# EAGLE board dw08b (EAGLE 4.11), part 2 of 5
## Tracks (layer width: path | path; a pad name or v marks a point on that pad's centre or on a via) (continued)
N_ADD00  (via drill 0.61) (continued)
  Bottom 0.305: v76.2,63.25 79.25,63.25 79.5,63.5 82.3,63.5 82.55,63.25 85.6,63.25 85.85,63.5 88.65,63.5 88.9,63.25 91.95,63.25 92.2,63.5 95,63.5 95.25,63.25 98.3,63.25 98.55,63.5 v99.57,63.5 | v99.57,72.39 99.82,72.64 116.59,72.64 117.09,72.14 119.38,72.14 119.89,72.64 126.49,72.64 127.76,71.37 156.46,71.37 v156.72,71.63 | v163.07,70.87 163.32,71.12 164.34,71.12 164.59,71.37 171.7,71.37 172.21,71.88 177.29,71.88 177.55,72.14 191.52,72.14 | 191.52,72.14 196.09,72.14 v196.34,71.88 | v197.61,60.45 199.64,60.45 200.15,59.94 v200.91,59.94 | v200.91,57.15 202.95,57.15 203.2,56.9 206.25,56.9 206.5,57.15 209.3,57.15 209.55,56.9 212.6,56.9 212.85,57.15 215.65,57.15 217.17,55.63 219.96,55.63 B07.D2 | v215.9,125.48 219.96,125.48 A07.D2 | v215.65,115.32 214.63,114.3 212.6,114.3 212.34,114.05 209.55,114.05 209.3,114.3 206.25,114.3 205.99,114.05 203.2,114.05 202.95,114.3 199.9,114.3 199.64,114.05 196.85,114.05 196.6,114.3 193.55,114.3 193.29,114.05 190.5,114.05 190.25,114.3 187.2,114.3 186.94,114.05 184.15,114.05 183.9,114.3 180.85,114.3 180.59,114.05 v177.8,114.05 | 191.52,72.14 v191.52,71.88
N_ADD01  (via drill 0.61)
  Top 0.305: v77.72,56.9 77.72,53.09 B19.E1 | v82.3,57.15 82.3,60.2 82.55,60.45 82.55,63.25 82.04,63.75 82.04,71.88 81.79,72.14 81.79,78.74 v82.04,78.99 | v163.83,72.14 v163.83,76.2 | v203.2,120.4 203.2,117.35 202.95,117.09 202.95,114.3 203.2,114.05 203.2,111 202.95,110.74 202.95,107.95 203.2,107.7 203.2,104.65 202.95,104.39 202.95,101.6 203.45,101.09 203.45,96.27 204.22,95.5 v204.22,92.2 | v201.93,88.9 v201.93,91.69 | v204.22,82.55 203.96,82.3 203.96,72.39 v204.22,72.14
  2 0.305: v201.93,88.9 203.2,87.63 203.2,85.6 202.69,85.09 202.95,84.84 202.95,83.82 v204.22,82.55
  15 0.305: v210.06,72.14 213.87,68.33 213.87,66.8 215.65,65.02 215.65,63.5 224.28,54.86 224.28,53.09 B07.E2
  Bottom 0.305: v77.72,56.9 79.25,56.9 79.5,57.15 v82.3,57.15 | v82.04,78.99 82.3,78.74 92.96,78.74 93.22,78.99 100.84,78.99 101.09,79.25 102.11,79.25 103.38,77.98 119.89,77.98 120.14,78.23 121.16,78.23 122.43,76.96 132.33,76.96 132.59,77.22 151.89,77.22 153.16,75.95 163.58,75.95 v163.83,76.2 | v163.83,72.14 171.45,72.14 171.96,72.64 177.04,72.64 177.29,72.9 199.14,72.9 199.9,72.14 v204.22,72.14 v210.06,72.14 | v203.2,120.4 205.99,120.4 206.25,120.65 209.3,120.65 209.55,120.4 212.34,120.4 212.6,120.65 215.65,120.65 215.9,120.4 218.69,120.4 220.47,122.17 223.27,122.17 A07.E2 | v204.22,92.2 203.2,92.2 202.69,91.69 v201.93,91.69
N_ADD02  (via drill 0.61)
  Top 0.305: v205.49,68.07 205.74,68.33 205.74,82.3 v205.49,82.55 | v205.49,85.85 v205.49,88.65 | v210.82,92.2 v210.82,95 | v226.57,95.25 226.57,98.55 225.55,99.57 225.55,110.74 224.03,112.27 224.03,112.78 223.77,113.03 223.77,115.32 A07.H2 | v74.68,52.07 74.68,49.78 B19.F1 | v18.8,127 18.8,130.05 19.05,130.3 19.05,133.1 18.8,133.35 v18.8,140.46 | v201.42,66.8 v201.42,68.83
  2 0.305: v205.49,68.07 211.33,62.23 211.33,61.72 212.85,60.2 212.85,59.18 224.28,47.75 224.28,46.74 B07.H2 | v74.68,52.07 74.68,52.58 76.45,54.36 76.2,54.61 76.2,55.88 68.58,63.5 v66.04,63.5 | v51.82,80.01 51.82,80.26 49.02,83.06 48.77,83.06 48.26,83.57 48.26,85.34 43.43,90.17 v41.66,90.17 | v46.48,140.46 46.48,141.22 48.77,143.51 66.29,143.51 88.65,121.16 89.66,121.16 91.69,119.13 91.69,117.86 99.06,110.49 99.31,110.49 105.92,103.89 107.19,103.89 107.7,103.38 107.7,102.62 v117.86,92.46
  15 0.305: v64.52,63.5 56.39,71.63 51.31,71.63 47.5,75.44 47.5,77.22 49.28,78.99 50.55,78.99 51.56,80.01 v51.82,80.01 | v46.99,94.74 46.23,94.74 37.85,103.12 37.85,104.65 38.35,105.16 38.1,105.41 38.1,107.7 v18.8,127 | v123.19,92.2 123.7,92.2 127.25,88.65 v128.02,88.65 | v148.08,88.39 148.84,87.63 148.84,87.38 158.24,77.98 159.77,77.98 171.2,66.55 171.2,64.01 173.74,61.47 174.24,61.47 v175.51,60.2
  Bottom 0.305: v205.49,82.55 206.5,83.57 206.5,85.34 205.99,85.85 v205.49,85.85 | v205.49,88.65 206.25,88.65 209.8,92.2 v210.82,92.2 | v210.82,95 212.6,95 212.85,95.25 215.65,95.25 215.9,95 218.95,95 219.2,95.25 222,95.25 222.25,95 225.3,95 225.55,95.25 v226.57,95.25 | v64.52,63.5 v66.04,63.5 | v41.66,90.17 41.91,90.42 42.16,90.42 43.18,91.44 43.43,91.44 43.69,91.69 43.94,91.69 v46.99,94.74 | v18.8,140.46 25.65,140.46 25.91,140.72 46.23,140.72 v46.48,140.46 | v117.86,92.46 118.36,92.46 118.62,92.2 119.38,92.2 119.63,92.46 122.94,92.46 v123.19,92.2 | v128.02,88.65 130.05,88.65 130.3,88.9 133.1,88.9 133.35,88.65 136.4,88.65 136.65,88.9 139.45,88.9 139.7,88.65 142.75,88.65 143,88.9 145.8,88.9 146.3,88.39 v148.08,88.39 | v175.51,60.2 175.77,59.94 177.55,59.94 178.05,60.45 180.85,60.45 181.36,59.94 183.9,59.94 184.4,60.45 186.69,60.45 187.2,59.94 189.99,59.94 197.1,67.06 201.17,67.06 v201.42,66.8 | v201.42,68.83 201.68,68.58 204.47,68.58 204.72,68.33 205.23,68.33 v205.49,68.07
N_ADD03  (via drill 0.61)
  Top 0.305: 225.3,50.55 225.3,44.7 223.77,43.18 223.77,40.39 B07.K2 | 225.3,50.55 225.3,65.53 223.77,67.06 223.77,81.28 222.5,82.55 222.5,104.39 223.77,105.66 223.77,108.97 A07.K2 | v74.17,25.4 74.17,28.7 73.15,29.72 73.15,30.48 73.41,30.73 73.41,30.99 73.66,31.24 73.66,32.26 76.2,34.8 76.2,37.85 75.95,38.1 75.95,40.89 77.72,42.67 77.72,45.47 B19.H1 | v134.37,23.37 135.64,24.64 135.64,25.65 136.4,26.42 136.4,28.19 136.14,28.45 136.14,32 v136.91,32.77 | v146.05,33.27 146.3,33.53 146.3,34.04 148.08,35.81 149.61,35.81 151.38,34.04 v151.64,34.04 | v224.03,50.8 224.28,50.55 225.3,50.55
  2 0.305: v113.03,3.56 113.03,7.37 v115.82,10.16 | v114.05,27.43 113.54,27.43 110.74,30.23 110.74,31.5 111.51,32.26 111.25,32.51 111.25,34.8 110.74,35.31 110.74,38.1 111.76,39.12 111.76,39.88 113.79,41.91 115.57,41.91 120.65,36.83 120.65,34.8 120.14,34.29 120.4,34.04 120.4,33.02 121.16,32.26 121.16,30.99 122.94,29.21 122.94,28.19 129.29,21.84 132.84,21.84 v134.37,23.37 | v136.91,32.77 138.68,34.54 139.45,34.54 140.21,35.31 140.46,35.05 142.75,35.05 144.02,33.78 145.54,33.78 v146.05,33.27 | v151.64,34.04 153.42,35.81 153.42,37.08 152.91,37.59 151.89,37.59 148.84,40.64 148.84,40.89 147.83,41.91 147.83,42.93 148.59,43.69 149.61,43.69 150.62,44.7 151.64,44.7 152.15,45.21 152.91,45.21 153.42,44.7 154.94,44.7 v155.7,45.47
  15 0.305: v78.49,24.38 87.63,15.24 87.88,15.24 88.65,14.48 88.65,14.22 v100.08,2.79 | v115.82,10.16 119.38,6.6 119.38,5.84 119.89,5.33 122.43,5.33 122.94,5.84 122.94,10.67 121.16,12.45 120.65,12.45 113.03,20.07 113.03,21.08 115.06,23.11 115.06,25.4 114.05,26.42 v114.05,27.43
  Bottom 0.305: v74.17,25.4 75.95,25.4 76.96,24.38 v78.49,24.38 | v100.08,2.79 100.33,3.05 108.71,3.05 109.22,2.54 112.01,2.54 v113.03,3.56 | v155.7,45.47 156.72,46.48 158.75,46.48 159.77,47.5 160.78,47.5 161.29,46.99 165.61,46.99 166.12,47.5 167.13,47.5 167.64,46.99 171.96,46.99 172.47,47.5 173.48,47.5 173.99,46.99 178.31,46.99 179.58,48.26 181.61,48.26 182.12,47.75 185.93,47.75 186.69,46.99 191.01,46.99 191.52,47.5 192.53,47.5 193.04,46.99 197.36,46.99 198.12,47.75 201.93,47.75 202.18,48.01 202.44,48.01 202.95,48.51 205.23,48.51 208.03,51.31 210.31,51.31 210.57,51.05 211.84,51.05 212.34,51.56 216.41,51.56 216.92,51.05 218.19,51.05 218.69,51.56 222.76,51.56 223.52,50.8 v224.03,50.8
N_ADD04  (via drill 0.61)
  Top 0.305: v223.52,38.1 223.52,36.32 223.77,36.07 223.77,34.04 B07.M2 | v229.62,54.1 v229.62,55.88 | v223.77,61.72 223.52,61.98 223.52,62.99 222.25,64.26 222.25,68.58 222.76,69.09 v222.76,70.61 | v248.16,70.87 248.41,71.12 248.41,74.68 v248.16,74.93 | v224.54,100.33 223.77,101.09 223.77,102.62 A07.M2 | v69.85,42.42 69.85,41.15 68.33,39.62 v68.33,38.1 | v10.16,67.31 10.16,69.85 9.91,70.1 9.91,77.72 v10.16,77.98 | v2.79,86.11 2.79,88.9 3.81,89.92 v3.81,92.2 | v10.67,103.38 v10.67,101.6 | v3.81,123.44 v3.81,120.4 | v12.7,123.95 12.7,126.75 12.45,127 12.45,130.05 12.7,130.3 12.7,133.1 12.45,133.35 v12.45,141.73 | v63.25,135.38 63.25,136.4 69.6,142.75 81.28,142.75 v81.28,135.38
  2 0.305: v229.62,55.88 v223.77,61.72 | v248.16,74.93 238.25,84.84 238.25,85.6 237.74,86.11 237.74,87.12 229.62,95.25 229.62,95.5 224.79,100.33 v224.54,100.33 | v33.27,44.2 32.77,44.2 25.15,51.82 25.15,52.32 v10.16,67.31 | v10.16,77.98 6.35,81.79 6.35,82.3 5.84,82.8 5.84,83.06 v2.79,86.11 | v10.67,103.38 2.79,111.25 2.79,115.06 3.05,115.32 3.05,117.09 2.79,117.35 2.79,119.38 v3.81,120.4 | v81.28,135.38 81.28,135.89 83.31,137.92 90.42,137.92 106.68,121.67 107.19,121.67 124.46,104.39 126.75,104.39 127.51,105.16 127.76,104.9 130.05,104.9 136.91,98.04 139.45,98.04 140.21,98.81 140.46,98.55 142.24,98.55 144.53,96.27 144.78,96.27 162.05,78.99 169.42,78.99 179.83,68.58 181.61,68.58 182.12,68.07 182.12,66.04 188.21,59.94 190.25,59.94 191.52,61.21 196.85,55.88 196.85,53.85 196.34,53.34 196.6,53.09 196.6,52.32 202.95,45.97 202.95,44.45 v204.22,43.18
  15 0.305: v218.19,43.43 v223.52,38.1 | v65.53,37.85 65.02,37.85 62.99,39.88 62.74,39.88 v58.42,44.2 | v30.99,141.73 39.62,133.1 41.4,133.1 42.67,134.37 43.69,134.37 44.2,134.87 44.2,135.38 46.99,138.18 57.66,138.18 v60.45,135.38
  Bottom 0.305: 218.95,44.2 228.85,54.1 v229.62,54.1 | 218.95,44.2 v218.19,43.43 | v222.76,70.61 223.01,70.36 229.11,70.36 229.36,70.1 240.79,70.1 241.55,70.87 v248.16,70.87 | v69.85,42.42 70.1,42.16 74.17,42.16 B19.J1 | v68.33,38.1 66.55,38.1 66.29,37.85 v65.53,37.85 | v58.42,44.2 57.15,44.2 56.9,44.45 53.85,44.45 53.59,44.2 50.8,44.2 50.55,44.45 47.5,44.45 47.24,44.2 44.45,44.2 44.2,44.45 41.15,44.45 40.89,44.2 38.1,44.2 37.85,44.45 34.8,44.45 34.54,44.2 v33.27,44.2 | v3.81,92.2 2.79,93.22 2.79,96.01 4.06,96.01 9.65,101.6 v10.67,101.6 | v3.81,123.44 6.1,123.44 6.6,123.95 v12.7,123.95 | v12.45,141.73 12.7,141.99 30.73,141.99 v30.99,141.73 | v63.25,135.38 v60.45,135.38 | v204.22,43.18 204.47,43.43 206.5,43.43 207.52,44.45 209.3,44.45 209.55,44.2 212.6,44.2 212.85,44.45 215.65,44.45 215.9,44.2 218.95,44.2
N_ADD05  (via drill 0.61)
  Top 0.305: v78.74,35.31 77.98,36.07 77.98,36.58 77.72,36.83 77.72,39.12 B19.K1 | v88.9,25.15 88.9,22.1 88.65,21.84 88.65,19.05 88.9,18.8 88.9,15.75 88.65,15.49 88.65,12.7 88.9,12.45 v88.9,6.35 | v120.4,6.35 120.65,6.6 v120.65,9.91 | v154.69,9.91 154.94,10.16 154.94,12.19 155.7,12.95 v155.7,19.05 | v209.3,19.05 209.3,21.08 210.06,21.84 210.06,24.89 v210.31,25.15 | v223.77,93.22 223.77,96.27 A07.P2 | v242.06,74.68 241.81,74.42 241.81,70.1 v242.06,69.85 | v221.74,69.6 221.49,69.34 221.49,64.01 222.76,62.74 222.76,60.45 v223.01,60.2 | v227.08,47.24 226.06,46.23 226.06,44.45 225.3,43.69 v225.3,42.67 | v229.87,38.1 228.6,36.83 228.6,34.8 228.35,34.54 228.35,31.75 228.6,31.5 228.6,28.45 228.35,28.19 v228.35,26.92
  2 0.305: v88.9,25.15 v78.74,35.31 | v223.77,93.22 228.6,88.39 228.6,88.14 229.87,86.87 230.12,86.87 240.28,76.71 240.54,76.71 242.06,75.18 v242.06,74.68 | v229.87,38.1 v225.3,42.67
  15 0.305: v223.01,60.2 221.49,58.67 225.04,55.12 225.04,54.1 229.62,49.53 v229.62,48.01
  Bottom 0.305: v88.9,6.35 89.15,6.1 120.14,6.1 v120.4,6.35 | v120.65,9.91 120.9,9.65 154.43,9.65 v154.69,9.91 | v155.7,19.05 158.5,19.05 158.75,18.8 161.8,18.8 162.05,19.05 164.85,19.05 165.1,18.8 168.15,18.8 168.4,19.05 171.2,19.05 171.45,18.8 174.5,18.8 174.75,19.05 177.55,19.05 177.8,18.8 180.85,18.8 181.1,19.05 183.9,19.05 184.15,18.8 187.2,18.8 187.45,19.05 190.25,19.05 190.5,18.8 193.55,18.8 193.8,19.05 196.6,19.05 196.85,18.8 199.9,18.8 200.15,19.05 202.95,19.05 203.2,18.8 206.25,18.8 206.5,19.05 v209.3,19.05 | v210.31,25.15 212.6,25.15 212.85,25.4 215.65,25.4 215.9,25.15 218.95,25.15 220.73,26.92 223.27,26.92 B07.P2 224.54,26.92 v228.35,26.92 | v242.06,69.85 241.55,69.34 229.11,69.34 228.85,69.6 v221.74,69.6 | v229.62,48.01 229.36,47.75 228.6,47.75 228.09,47.24 v227.08,47.24
N_ADD06  (via drill 0.61)
  Top 0.305: v78.99,36.58 79.76,35.81 79.76,30.73 79.5,30.48 79.5,29.72 79.76,29.46 79.76,24.38 79.5,24.13 79.5,12.7 78.99,12.19 v78.99,4.32 | v146.05,4.83 146.05,12.45 145.8,12.7 v145.8,16 | v171.2,15.49 171.2,12.7 171.45,12.45 v171.45,8.13 | v215.9,8.64 215.9,12.45 215.65,12.7 215.65,15.75 215.9,16 v215.9,18.8 | v218.19,85.85 v218.19,88.65 | v178.82,82.3 178.56,82.04 178.56,71.37 v178.82,71.12 | v165.1,70.36 164.85,70.1 164.85,63.5 165.1,63.25 165.1,60.2 164.85,59.94 164.85,57.15 165.1,56.9 165.1,53.85 164.85,53.59 164.85,50.8 165.1,50.55 165.1,47.5 164.85,47.24 164.85,44.45 165.1,44.2 165.1,41.15 164.85,40.89 164.85,38.1 165.1,37.85 165.1,34.8 164.85,34.54 164.85,31.75 165.1,31.5 165.1,28.45 164.85,28.19 164.85,25.4 165.1,25.15 165.1,22.1 164.85,21.84 164.85,19.05 165.1,18.8 v165.1,16
  Bottom 0.305: v78.99,36.58 75.18,36.58 B19.L1 | v78.99,4.32 79.25,4.57 122.68,4.57 123.19,5.08 145.8,5.08 v146.05,4.83 | v145.8,16 v165.1,16 167.89,16 168.4,15.49 v171.2,15.49 | v171.45,8.13 171.7,7.87 201.93,7.87 202.44,8.38 211.58,8.38 211.84,8.64 v215.9,8.64 | v215.9,18.8 218.95,18.8 219.71,19.56 222.76,19.56 B07.S2 | v218.19,88.65 218.69,88.65 220.47,90.42 223.27,90.42 A07.S2 | v218.19,85.85 215.9,85.85 213.61,83.57 213.36,83.57 212.09,82.3 209.55,82.3 209.3,82.55 207.01,82.55 205.99,81.53 203.71,81.53 202.69,82.55 199.9,82.55 199.64,82.3 196.85,82.3 196.6,82.55 193.55,82.55 193.29,82.3 190.5,82.3 190.25,82.55 187.2,82.55 186.94,82.3 184.15,82.3 183.9,82.55 180.85,82.55 180.59,82.3 v178.82,82.3 | v178.82,71.12 172.47,71.12 171.96,70.61 165.35,70.61 v165.1,70.36
N_ADD07  (via drill 0.61)
  Top 0.305: 222,80.01 222,79.25 220.73,77.98 220.73,63.75 222,62.48 222,22.1 220.73,20.83 220.73,18.03 B07.T2 | 222,80.01 222,82.04 220.73,83.31 220.73,86.61 A07.T2 | v76.2,22.86 76.2,25.15 75.95,25.4 75.95,28.19 76.2,28.45 76.2,31.75 B19.M1 | v90.42,16 91.44,17.02 91.44,18.03 91.69,18.29 91.69,19.81 92.2,20.32 92.2,24.13 92.46,24.38 92.46,25.4 v93.98,26.92 | v120.14,57.4 119.89,57.66 119.89,60.71 120.4,61.21 120.4,62.48 119.63,63.25 119.63,70.87 v120.4,71.63 | 222,80.01 v222.25,80.01
  2 0.305: v93.98,26.92 97.79,30.73 98.3,30.73 100.33,32.77 100.84,32.77 101.35,33.27 101.35,34.29 100.58,35.05 99.57,35.05 98.55,36.07 98.55,37.08 99.57,38.1 101.35,38.1 101.6,37.85 103.38,37.85 104.9,39.37 104.9,41.15 104.39,41.66 104.39,44.2 106.17,45.97 105.92,46.23 105.92,47.75 98.55,55.12 98.55,56.13 99.57,57.15 101.35,57.15 101.6,56.9 102.87,56.9 105.66,54.1 107.19,54.1 v108.97,55.88 | v222.25,80.01 v228.35,73.91
  15 0.305: v85.6,15.75 v78.49,22.86
  Bottom 0.305: v78.49,22.86 v76.2,22.86 | v85.6,15.75 85.85,15.49 88.65,15.49 89.15,16 v90.42,16 | v108.97,55.88 109.22,56.13 111.25,56.13 112.52,57.4 116.59,57.4 117.09,57.91 119.63,57.91 v120.14,57.4 | v120.4,71.63 120.65,71.88 126.24,71.88 127.51,70.61 157.23,70.61 157.48,70.87 161.04,70.87 163.32,73.15 164.34,73.15 164.59,72.9 169.16,72.9 170.43,74.17 176.53,74.17 176.78,74.42 223.77,74.42 224.28,73.91 v228.35,73.91
N_ADD08  (via drill 0.61)
  Top 0.305: A07.V2 219.96,80.52 219.2,79.76 v219.2,40.64 219.2,16 220.73,14.48 220.73,11.68 B07.V2 | v64.52,61.98 v64.52,60.45 | v40.89,123.95 40.89,126.49 42.16,127.76 42.16,129.03 42.42,129.29 v42.42,130.05 | v66.55,134.11 66.8,134.37 66.8,138.94 69.85,141.99 79.5,141.99 v79.5,134.11 | v117.6,117.6 v117.6,114.05 | v152.15,110.74 152.15,107.95 152.4,107.7 v152.4,105.66
  2 0.305: v69.85,29.97 69.85,30.48 64.26,36.07 63.75,36.07 63.25,36.58 63.25,38.35 59.18,42.42 59.18,42.67 58.67,43.18 57.91,43.18 52.83,48.26 51.82,48.26 50.8,49.28 50.8,49.53 49.28,51.05 49.28,52.58 46.48,55.37 46.48,55.88 44.96,57.4 42.42,57.4 41.91,57.91 41.91,58.42 39.88,60.45 v39.37,60.45 | v64.52,61.98 63.5,62.99 63.5,63.25 63.25,63.5 63.25,66.8 58.42,71.63 58.42,72.64 58.93,73.15 60.45,73.15 61.72,71.88 65.02,71.88 70.1,76.96 71.88,76.96 73.41,78.49 71.12,80.77 71.12,81.03 52.83,99.31 52.83,100.58 34.54,118.87 34.54,120.4 35.31,121.16 35.05,121.41 35.05,122.43 v33.53,123.95 | v82.55,134.11 83.06,134.11 84.07,133.1 86.36,133.1 86.87,133.6 87.12,133.35 87.88,133.35 90.93,130.3 91.95,130.3 100.84,121.41 102.11,121.41 103.12,120.4 103.63,120.4 104.14,119.89 104.14,119.38 109.47,114.05 v109.98,114.05
  15 0.305: v46.74,130.3 46.99,130.3 48.26,129.03 49.78,129.03 54.1,133.35 56.13,133.35 56.39,133.1 60.96,133.1 61.47,133.6 61.47,135.13 62.99,136.65 65.28,136.65 66.8,135.13 66.8,134.37 v66.55,134.11 | v122.68,117.6 123.44,118.36 123.7,118.11 124.46,118.11 131.83,110.74 132.84,110.74 v134.37,112.27 | v163.83,103.89 171.2,96.52 171.2,95.25 175.01,91.44 175.01,91.19 181.1,85.09 181.1,82.55 180.34,81.79 180.59,81.53 180.59,80.01 189.48,71.12 189.99,71.12 196.6,64.52 196.6,63.5 199.64,60.45 199.64,59.69 201.17,58.17 201.68,58.17 v219.2,40.64
  Bottom 0.305: v69.85,29.97 70.1,30.23 73.91,30.23 B19.N1 | v39.37,60.45 46.99,60.45 47.5,59.94 50.55,59.94 51.05,60.45 53.34,60.45 53.85,59.94 56.9,59.94 57.4,60.45 59.69,60.45 60.2,59.94 63.25,59.94 63.75,60.45 v64.52,60.45 | v40.89,123.95 v33.53,123.95 | v42.42,130.05 42.67,129.79 44.2,129.79 44.7,130.3 v46.74,130.3 | v82.55,134.11 v79.5,134.11 | v109.98,114.05 111,114.05 111.25,114.3 114.05,114.3 114.3,114.05 v117.6,114.05 | v117.6,117.6 119.38,117.6 119.63,117.86 122.43,117.86 v122.68,117.6 | v134.37,112.27 136.65,112.27 137.67,111.25 138.43,111.25 138.68,111.51 139.19,111.51 139.7,112.01 141.73,112.01 141.99,112.27 143,112.27 143.51,111.76 143.51,109.73 145.03,109.73 146.56,111.25 148.84,111.25 149.35,110.74 v152.15,110.74 | v152.4,105.66 155.96,105.66 156.72,104.9 161.54,104.9 162.56,103.89 v163.83,103.89
N_ADD09  (via drill 0.61)
  Top 0.305: A08.D2 208.03,124.71 208.03,121.41 206.5,119.89 206.5,61.47 208.03,59.94 208.03,56.13 B08.D2 | v20.32,123.95 20.57,124.21 v20.57,126.75 | v44.2,127 44.2,129.03 45.21,130.05 45.21,131.83 v45.47,132.08 | v55.12,134.87 54.86,135.13 54.86,138.43 59.94,143.51 86.11,143.51 v86.11,135.38 | v110.74,131.06 110.74,133.1 111.25,133.6 v111.25,134.11 | v114.05,134.11 114.05,138.68 v115.57,140.21
  2 0.305: v46.74,132.08 48.01,133.35 50.55,133.35 50.8,133.1 53.34,133.1 v55.12,134.87
  15 0.305: v69.09,25.91 55.12,39.88 55.12,41.4 41.15,55.37 40.89,55.37 31.5,64.77 31.5,67.06 27.18,71.37 27.18,73.66 24.64,76.2 24.64,78.23 21.84,81.03 21.84,82.3 22.61,83.06 22.35,83.31 22.35,85.6 20.57,87.38 v20.57,88.65 | v19.3,92.2 19.3,93.73 16,97.03 16,98.3 15.49,98.81 15.49,100.84 v15.24,101.09 | v36.32,107.95 36.32,108.46 20.83,123.95 v20.32,123.95 | v86.11,135.38 87.63,133.86 87.63,133.6 90.93,130.3 91.95,130.3 92.46,129.79 93.98,129.79 v94.49,130.3 | v115.57,140.21 116.08,140.21 118.87,143 v118.87,143.26 | v148.08,142.24 153.67,136.65 154.69,136.65 161.04,130.3 161.8,130.3 166.37,125.73 168.15,125.73 169.42,127 170.18,127 v172.97,124.21
  Bottom 0.305: v69.09,25.91 70.61,25.91 70.87,25.65 72.14,25.65 73.41,26.92 77.22,26.92 B19.P1 | v20.57,88.65 21.08,88.65 22.35,89.92 22.35,91.69 21.84,92.2 v19.3,92.2 | v15.24,101.09 15.75,101.6 18.8,101.6 19.05,101.35 22.1,101.35 22.35,101.6 25.15,101.6 25.4,101.35 28.45,101.35 35.05,107.95 v36.32,107.95 | v20.57,126.75 21.84,126.75 22.35,127.25 43.94,127.25 v44.2,127 | v46.74,132.08 v45.47,132.08 | v94.49,130.3 97.79,130.3 98.3,129.79 101.35,129.79 101.85,130.3 104.14,130.3 104.65,129.79 107.7,129.79 108.2,130.3 109.47,130.3 109.98,130.81 110.49,130.81 v110.74,131.06 | v114.05,134.11 v111.25,134.11 | v118.87,143.26 119.13,143.51 134.87,143.51 136.14,142.24 137.16,142.24 137.67,142.75 147.57,142.75 v148.08,142.24 | v172.97,124.21 175.51,124.21 175.77,123.95 201.93,123.95 202.18,124.21 203.71,124.21 204.98,125.48 207.26,125.48 A08.D2
N_ADD10  (via drill 0.61)
  Top 0.305: v76.2,5.33 76.2,12.45 75.95,12.7 75.95,15.49 76.2,15.75 76.2,18.8 74.68,20.32 74.68,23.11 B19.R1 | v147.83,5.59 148.08,5.84 148.08,12.19 v147.83,12.45 | v190.25,12.7 190.25,15.75 190.5,16 190.5,18.8 190.25,19.05 190.25,22.1 190.5,22.35 190.5,25.15 190.25,25.4 190.25,28.45 190.5,28.7 190.5,31.5 190.25,31.75 190.25,34.8 190.5,35.05 190.5,37.85 190.25,38.1 190.25,41.15 190.5,41.4 190.5,44.2 190.25,44.45 190.25,47.5 190.5,47.75 v190.5,50.04 | v209.55,107.95 209.3,108.2 209.3,110.74 209.55,111 209.55,114.05 209.3,114.3 209.3,117.09 209.55,117.35 209.55,117.86 211.07,119.38 211.07,121.67 A08.E2 | v190.75,107.7 190.75,102.62 191.52,101.85 v191.52,98.55 | v186.18,92.2 v186.18,95 | v183.39,85.85 183.64,85.6 183.64,82.3 184.91,81.03 184.91,67.82 v184.66,67.56 | v181.1,67.56 181.1,63.5 180.34,62.74 180.34,61.72 v180.09,61.47
  2 0.305: v180.09,61.47 183.9,57.66 183.9,57.15 190.75,50.29 v190.5,50.04
  Bottom 0.305: v76.2,5.33 122.43,5.33 122.94,5.84 147.57,5.84 v147.83,5.59 | v147.83,12.45 149.1,12.45 149.35,12.7 152.15,12.7 152.4,12.45 155.45,12.45 155.7,12.7 158.5,12.7 158.75,12.45 161.8,12.45 162.05,12.7 164.85,12.7 165.1,12.45 168.15,12.45 168.4,12.7 171.2,12.7 171.45,12.45 174.5,12.45 174.75,12.7 177.55,12.7 177.8,12.45 180.85,12.45 181.1,12.7 183.9,12.7 184.15,12.45 187.2,12.45 187.45,12.7 v190.25,12.7 | v190.5,50.04 190.75,50.29 193.04,50.29 193.55,50.8 196.6,50.8 196.85,50.55 199.9,50.55 200.15,50.8 202.95,50.8 203.2,50.55 206.25,50.55 207.77,52.07 208.79,52.07 209.04,52.32 210.57,52.32 B08.E2 | v209.55,107.95 206.25,107.95 205.99,107.7 203.2,107.7 202.95,107.95 199.9,107.95 199.64,107.7 196.85,107.7 196.6,107.95 193.55,107.95 193.29,107.7 v190.75,107.7 | v191.52,98.55 190.5,98.55 186.94,95 v186.18,95 | v186.18,92.2 185.42,92.2 183.9,90.68 183.9,88.9 184.15,88.65 184.15,85.85 v183.39,85.85 | v181.1,67.56 v184.66,67.56
N_ADD11  (via drill 0.61)
  Top 0.305: v77.72,19.05 77.72,20.07 B19.S1 | v121.67,16 v121.67,18.8 | v128.27,18.8 v128.27,16 | v150.37,21.84 v150.37,19.05 | v171.45,22.35 171.45,25.15 171.2,25.4 171.2,28.45 171.45,28.7 171.45,31.5 171.2,31.75 171.2,34.8 171.45,35.05 171.45,37.85 171.2,38.1 171.2,41.15 171.45,41.4 v171.45,44.2 | v212.34,104.9 212.34,107.44 212.85,107.95 212.85,110.74 212.34,111.25 212.34,115.06 211.84,115.57 A08.H2 | v189.23,101.6 v189.23,104.39 | v158.75,101.35 158.75,98.3 158.5,98.04 158.5,95.25 158.75,95 158.75,91.95 158.5,91.69 158.5,88.9 158.75,88.65 158.75,85.6 158.5,85.34 158.5,82.55 158.75,82.3 v158.75,78.99 | v155.7,78.99 155.7,68.83 155.96,68.58 155.96,62.48 155.7,62.23 v155.7,59.94
  2 0.305: v155.7,59.94 v171.45,44.2
  Bottom 0.305: v77.72,19.05 82.3,19.05 82.55,18.8 85.6,18.8 85.85,19.05 88.65,19.05 88.9,18.8 91.95,18.8 92.2,19.05 95,19.05 95.25,18.8 98.3,18.8 98.55,19.05 101.35,19.05 101.6,18.8 104.65,18.8 104.9,19.05 107.7,19.05 107.95,18.8 111,18.8 111.25,19.05 114.05,19.05 114.3,18.8 117.35,18.8 117.6,19.05 120.4,19.05 120.65,18.8 v121.67,18.8 | v121.67,16 123.19,16 123.7,15.49 126.75,15.49 127.25,16 v128.27,16 | v128.27,18.8 130.05,18.8 130.3,19.05 133.1,19.05 133.35,18.8 136.4,18.8 136.65,19.05 139.45,19.05 139.7,18.8 142.75,18.8 143,19.05 145.8,19.05 146.05,18.8 149.1,18.8 149.35,19.05 v150.37,19.05 | v150.37,21.84 152.15,21.84 152.65,22.35 v171.45,22.35 | v171.45,44.2 174.5,44.2 174.75,44.45 177.55,44.45 177.8,44.2 180.85,44.2 181.1,44.45 183.9,44.45 184.15,44.2 187.2,44.2 187.45,44.45 190.25,44.45 190.5,44.2 193.55,44.2 193.8,44.45 196.6,44.45 196.85,44.2 199.9,44.2 200.15,44.45 202.95,44.45 203.2,44.2 206.25,44.2 208.03,45.97 210.57,45.97 B08.H2 | v212.34,104.9 190.5,104.9 189.99,104.39 v189.23,104.39 | v189.23,101.6 187.2,101.6 186.94,101.35 184.15,101.35 183.9,101.6 180.85,101.6 180.59,101.35 177.8,101.35 177.55,101.6 174.5,101.6 174.24,101.35 171.45,101.35 171.2,101.6 168.15,101.6 167.89,101.35 165.1,101.35 164.85,101.6 161.8,101.6 161.54,101.35 v158.75,101.35 | v158.75,78.99 v155.7,78.99
N_BAC00  (via drill 0.61)
  Top 0.305: A01.D2 296.93,124.71 296.93,121.41 295.4,119.89 295.4,61.47 296.93,59.94 296.93,56.13 B01.D2 | v160.53,50.04 160.27,50.29 160.27,51.82 B12.E2 | v205.99,11.43 205.99,11.94 208.03,13.97 208.03,15.49 v208.28,15.75 | v263.65,18.8 263.65,30.48 263.91,30.73 263.91,34.29 v264.16,34.54 | v278.13,44.45 v278.13,47.24
  15 0.305: v160.53,50.04 160.78,50.04 179.32,31.5 180.85,31.5 181.36,32 181.61,31.75 183.9,31.75 v204.22,11.43
  Bottom 0.305: v205.99,11.43 v204.22,11.43 | v208.28,15.75 209.3,15.75 209.55,16 214.63,16 214.88,16.26 215.14,16.26 216.92,18.03 219.2,18.03 219.96,18.8 225.3,18.8 225.55,19.05 228.35,19.05 228.6,18.8 231.65,18.8 231.9,19.05 234.7,19.05 234.95,18.8 238,18.8 238.25,19.05 241.05,19.05 241.3,18.8 244.35,18.8 244.6,19.05 247.4,19.05 247.65,18.8 250.7,18.8 250.95,19.05 253.75,19.05 254,18.8 257.05,18.8 257.3,19.05 260.1,19.05 260.35,18.8 v263.65,18.8 | v264.16,34.54 266.45,34.54 276.35,44.45 v278.13,44.45 | v278.13,47.24 279.15,47.24 279.65,47.75 284.48,47.75 284.73,48.01 286.26,48.01 288.04,49.78 288.8,49.78 289.05,50.04 289.31,50.04 289.81,50.55 289.81,53.59 291.85,53.59 293.88,55.63 296.16,55.63 B01.D2
N_BAC01  (via drill 0.61)
  Top 0.305: v162.31,77.98 162.05,77.72 162.05,51.05 161.54,50.55 161.54,46.99 161.04,46.48 B12.H2 | v278.13,77.98 278.38,77.72 278.38,64.77 v278.13,64.52 | v292.1,120.4 292.1,117.35 291.85,117.09 291.85,114.3 292.1,114.05 292.1,111 291.85,110.74 291.85,107.95 292.1,107.7 292.1,104.65 291.85,104.39 291.85,101.6 292.1,101.35 v292.1,98.04 | v289.05,98.04 289.05,82.55 288.54,82.04 v288.54,78.23
  15 0.305: v278.13,64.52 v290.83,51.82
  Bottom 0.305: v162.31,77.98 175.26,77.98 175.51,78.23 252.98,78.23 253.24,77.98 254.25,77.98 254.51,78.23 270.26,78.23 270.51,77.98 v278.13,77.98 278.38,78.23 v288.54,78.23 | v290.83,51.82 292.35,51.82 293.12,51.05 294.39,51.05 295.15,51.82 296.67,51.82 296.93,52.07 297.69,52.07 297.94,52.32 299.47,52.32 B01.E2 | v292.1,120.4 294.89,120.4 296.67,122.17 299.47,122.17 A01.E2 | v289.05,98.04 v292.1,98.04
N_BAC02  (via drill 0.61)
  Top 0.305: v158.75,39.62 158.75,44.2 158.5,44.45 158.5,47.5 158.75,47.75 158.75,50.55 158.5,50.8 158.5,53.85 158.75,54.1 158.75,56.9 158.5,57.15 158.5,60.2 158.75,60.45 158.75,63.25 158.5,63.5 158.5,68.58 159.51,69.6 159.51,76.71 v159.26,76.96 | v277.11,76.96 277.62,76.45 277.62,67.06 v277.37,66.8 | v304.55,115.82 304.55,114.3 304.8,114.05 304.8,111 304.55,110.74 304.55,107.95 304.8,107.7 304.8,104.65 304.55,104.39 304.55,101.6 304.8,101.35 304.8,98.3 304.55,98.04 304.55,95.25 304.8,95 304.8,92.2 303.53,90.93 v303.53,88.9 | v293.12,82.3 292.86,82.04 292.86,77.47 v293.12,77.22
  15 0.305: v277.37,66.8 279.15,65.02 279.15,64.52 290.83,52.83 291.34,52.83 296.93,47.24 298.7,47.24 299.47,46.48 B01.H2
  Bottom 0.305: v158.75,39.62 159.77,39.62 B12.K2 | v159.26,76.96 162.81,76.96 163.07,77.22 175.51,77.22 175.77,77.47 252.73,77.47 252.98,77.22 254.51,77.22 254.76,77.47 270,77.47 270.26,77.22 276.86,77.22 v277.11,76.96 278.64,76.96 279.15,77.47 287.78,77.47 288.04,77.22 v293.12,77.22 | v304.55,115.82 300.74,115.82 A01.H2 | v303.53,88.9 301.5,88.9 300.48,87.88 299.47,87.88 298.45,86.87 298.45,85.85 294.89,82.3 v293.12,82.3
N_BAC03  (via drill 0.61)
  Top 0.305: A01.K2 299.97,108.97 299.97,105.66 298.7,104.39 298.7,82.55 299.97,81.28 299.97,67.06 301.5,65.53 301.5,44.7 299.97,43.18 299.97,40.39 B01.K2 299.97,39.12 299.97,35.56 v299.47,35.05 | v160.53,37.85 160.27,37.59 160.27,34.04 B12.M2 | v163.07,38.1 163.07,41.4 162.05,42.42 v162.05,44.45 | v290.07,31.75 v290.07,34.54
  15 0.305: v171.45,45.72 172.97,44.2 175.26,44.2 175.77,44.7 176.02,44.45 177.55,44.45 177.8,44.2 180.85,44.2 184.4,47.75 187.2,47.75 197.1,37.85 199.9,37.85 200.41,38.35 200.66,38.1 202.69,38.1 212.6,28.19 v213.87,28.19
  Bottom 0.305: v160.53,37.85 161.8,37.85 162.05,38.1 v163.07,38.1 | v162.05,44.45 164.85,44.45 165.1,44.2 168.15,44.2 169.67,45.72 v171.45,45.72 | v213.87,28.19 215.65,28.19 216.15,28.7 227.33,28.7 227.58,28.96 227.84,28.96 229.62,30.73 231.9,30.73 232.92,31.75 234.7,31.75 234.95,31.5 238,31.5 238.25,31.75 241.05,31.75 241.3,31.5 244.35,31.5 244.6,31.75 253.75,31.75 254,31.5 257.05,31.5 257.3,31.75 260.1,31.75 260.35,31.5 263.4,31.5 263.65,31.75 266.45,31.75 266.7,31.5 269.75,31.5 270,31.75 279.15,31.75 279.4,31.5 282.45,31.5 282.7,31.75 v290.07,31.75 | v290.07,34.54 291.85,34.54 292.35,35.05 v299.47,35.05
N_BAC04  (via drill 0.61)
  Top 0.305: v158.75,26.92 158.75,22.1 158.5,21.84 158.5,19.05 158.75,18.8 158.75,15.75 158.5,15.49 158.5,12.7 158.75,12.45 v158.75,1.27 | v288.54,1.27 288.54,12.45 289.05,12.95 v289.05,21.84 | v294.89,22.35 294.89,24.89 295.66,25.65 295.66,29.46 295.4,29.72 v295.4,33.27 295.66,33.53 295.66,35.81 295.4,36.07 295.4,36.83 295.66,37.08 295.66,42.16 295.4,42.42 295.4,43.18 295.66,43.43 295.66,48.51 295.4,48.77 295.4,49.53 295.66,49.78 295.66,54.86 295.4,55.12 v295.4,59.94 | v300.99,67.56 300.74,67.82 300.74,81.53 301.75,82.55 301.75,98.04 301.24,98.55 301.24,102.36 300.74,102.87 A01.M2 | v298.2,67.56 298.2,63.5 298.96,62.74 298.96,60.71 v299.21,60.45
  Bottom 0.305: v158.75,26.92 159.77,26.92 B12.P2 | v158.75,1.27 159,1.02 288.29,1.02 v288.54,1.27 | v289.05,21.84 291.85,21.84 292.35,22.35 v294.89,22.35 | v295.4,33.27 299.47,33.27 B01.M2 | v298.2,67.56 v300.99,67.56 | v299.21,60.45 298.45,60.45 297.94,59.94 v295.4,59.94
N_BAC05  (via drill 0.61)
  Top 0.305: v161.54,2.03 161.54,12.19 162.05,12.7 162.05,15.49 161.54,16 161.54,19.81 161.04,20.32 B12.S2 | v289.56,2.29 289.31,2.54 289.31,8.89 v289.56,9.14 | v298.45,9.14 298.45,12.45 298.2,12.7 298.2,15.75 298.45,16 298.45,18.8 298.2,19.05 298.2,21.08 298.96,21.84 298.96,25.91 B01.P2 299.97,27.69 299.97,29.97 301.75,31.75 301.75,43.18 302.01,43.43 302.01,43.69 302.26,43.94 302.26,45.97 v302.51,46.23 | v292.1,95 292.1,91.95 291.85,91.69 291.85,88.9 292.1,88.65 292.1,85.6 291.85,85.34 291.85,82.55 292.1,82.3 292.1,68.58 290.83,67.31 v290.83,63.5 | v287.78,60.96 v287.78,63.25
  2 0.305: v302.51,46.23 v287.78,60.96
  Bottom 0.305: v161.54,2.03 161.8,1.78 287.53,1.78 288.04,2.29 v289.56,2.29 | v289.56,9.14 v298.45,9.14 | v292.1,95 294.89,95 296.67,96.77 299.47,96.77 A01.P2 | v290.83,63.5 288.8,63.5 288.54,63.25 v287.78,63.25
N_BAC06  (via drill 0.61)
  Top 0.305: v304.55,90.42 304.55,88.9 304.8,88.65 304.8,85.85 304.55,85.6 304.55,82.55 304.8,82.3 304.8,79.25 304.55,78.99 304.55,63.5 304.8,63.25 304.8,60.45 304.55,60.2 304.55,57.15 304.8,56.9 304.8,54.1 304.55,53.85 304.55,50.8 304.8,50.55 304.8,47.75 304.55,47.5 304.55,44.45 304.8,44.2 304.8,41.4 304.55,41.15 304.55,38.1 304.8,37.85 304.8,35.05 304.55,34.8 304.55,31.75 304.8,31.5 304.8,28.7 304.55,28.45 304.55,25.4 304.8,25.15 304.8,22.35 304.55,22.1 v304.55,20.57 304.55,19.05 304.8,18.8 304.8,16 304.55,15.75 304.55,12.7 304.8,12.45 v304.8,7.62 | v148.34,55.88 148.34,52.83 B13.E2 | v201.42,25.4 202.95,26.92 202.95,28.45 203.2,28.7 v203.2,30.48
  2 0.305: v148.34,55.88 149.61,57.15 151.89,57.15 168.15,40.89 170.94,40.89 174.5,44.45 176.53,44.45 177.8,43.18 177.8,41.15 177.29,40.64 177.55,40.39 177.55,39.12 v180.09,36.58 | v205.49,30.48 205.74,30.48 208.03,28.19 209.3,28.19 210.06,28.96 210.31,28.7 211.33,28.7 v217.68,22.35
  15 0.305: v180.09,36.58 191.52,25.15 193.55,25.15 194.06,25.65 194.31,25.4 196.6,25.4 196.85,25.15 198.63,25.15 199.64,26.16 200.66,26.16 v201.42,25.4 | v237.24,22.35 237.49,22.35 v253.24,6.6
  Bottom 0.305: v304.55,20.57 300.74,20.57 B01.S2 | v304.55,90.42 300.74,90.42 A01.S2 | v205.49,30.48 v203.2,30.48 | v217.68,22.35 218.69,22.35 219.96,21.08 220.98,21.08 222.25,22.35 v237.24,22.35 | v253.24,6.6 253.49,6.35 274.07,6.35 274.83,7.11 293.88,7.11 294.39,7.62 v304.8,7.62
N_BAC07  (via drill 0.61)
  Top 0.305: A01.T2 296.93,86.61 296.93,83.31 298.2,82.04 298.2,79.25 296.93,77.98 296.93,63.75 298.2,62.48 298.2,22.1 296.93,20.83 296.93,18.03 B01.T2 296.93,16.76 296.93,13.97 294.89,11.94 v294.89,6.6 | v148.34,50.04 148.34,46.48 B13.H2 | v218.69,10.67 218.69,12.45 219.2,12.95 v219.2,13.97
  2 0.305: v148.34,50.04 148.59,50.04 149.35,50.8 152.15,50.8 161.04,41.91 162.56,41.91 166.62,37.85 166.62,37.34 167.89,36.07 168.15,36.07 v173.74,30.48
  15 0.305: v173.74,30.48 173.99,30.48 176.28,28.19 177.55,28.19 178.82,29.46 184.91,23.37 185.42,23.37 186.44,22.35 187.2,22.35 187.71,21.84 190.25,21.84 191.52,23.11 203.2,11.43 203.2,10.92 204.72,9.4 213.61,9.4 213.87,9.14 214.88,9.14 216.41,10.67 v216.92,10.67 | v222.25,13.97 229.11,7.11 233.93,7.11 v234.95,6.1
  Bottom 0.305: v218.69,10.67 v216.92,10.67 | v222.25,13.97 v219.2,13.97 | v234.95,6.1 235.2,6.35 249.68,6.35 250.44,5.59 274.32,5.59 275.08,6.35 294.64,6.35 v294.89,6.6
N_BAC08  (via drill 0.61)
  Top 0.305: v292.1,11.18 292.1,12.45 291.85,12.7 291.85,15.75 292.1,16 292.1,18.8 291.85,19.05 291.85,22.1 292.1,22.35 292.1,25.15 291.85,25.4 291.85,28.45 292.1,28.7 292.1,31.5 291.85,31.75 291.85,34.8 292.1,35.05 292.1,37.85 291.85,38.1 291.85,41.15 292.1,41.4 292.1,44.2 291.85,44.45 291.85,47.5 292.1,47.75 292.1,50.55 291.85,50.8 291.85,53.85 292.1,54.1 292.1,56.9 291.85,57.15 291.85,60.2 292.1,60.45 292.1,63.25 291.85,63.5 v291.85,66.8 | v294.39,66.8 294.64,67.06 294.64,80.77 v294.39,81.03 | v246.38,8.89 v246.38,5.08 | v296.93,5.84 296.93,10.41 B01.V2
  2 0.305: v139.45,57.91 139.45,57.4 140.72,56.13 140.72,55.12 139.7,54.1 137.67,54.1 137.41,54.36 136.65,53.59 136.65,52.58 137.16,52.07 138.18,52.07 139.7,50.55 139.95,50.55 140.72,49.78 140.72,49.53 147.07,43.18 147.07,41.66 148.08,40.64 148.08,40.39 B13.K2 | v186.18,24.13 187.71,25.65 187.96,25.4 190.25,25.4 190.5,25.15 193.55,25.15 194.06,25.65 194.31,25.4 195.58,25.4 v198.37,22.61
  15 0.305: v139.45,57.91 140.46,56.9 142.75,56.9 143.26,57.4 143.51,57.15 144.78,57.15 149.35,52.58 149.35,51.82 150.37,50.8 152.15,50.8 154.69,48.26 156.21,48.26 166.62,37.85 166.62,37.34 167.89,36.07 168.4,36.07 172.97,31.5 174.5,31.5 175.01,32 175.26,31.75 177.55,31.75 185.17,24.13 v186.18,24.13 | v205.99,22.35 206.25,22.35 208.53,20.07 209.8,20.07 214.63,15.24 v214.63,14.99 | v222.25,16 224.03,16 v231.39,8.64
  Bottom 0.305: v292.1,11.18 296.16,11.18 B01.V2 | v291.85,66.8 v294.39,66.8 | v294.39,81.03 296.16,81.03 A01.V2 | v198.37,22.61 200.91,22.61 201.17,22.35 v205.99,22.35 | v214.63,14.99 215.14,15.49 215.39,15.49 215.9,16 v222.25,16 | v231.39,8.64 246.13,8.64 v246.38,8.89 | v246.38,5.08 246.63,4.83 274.57,4.83 275.34,5.59 296.67,5.59 v296.93,5.84
N_BAC09  (via drill 0.61)
  Top 0.305: A02.D2 284.23,124.71 284.23,121.41 282.7,119.89 282.7,61.47 284.23,59.94 284.23,56.13 B02.D2 | v149.35,27.18 149.35,27.69 147.57,29.46 147.57,32.77 B13.M2 | v301.24,4.83 301.24,12.45 301.75,12.95 301.75,30.73 302.51,31.5 302.51,33.02 v302.77,33.27
  2 0.305: v166.88,11.18 v151.13,26.92 | v302.77,33.27 289.81,46.23 289.31,46.23 285.75,49.78 285.75,50.55 285.5,50.8 285.5,53.85 284.48,54.86 B02.D2
  15 0.305: v166.88,11.18 177.04,1.02 210.06,1.02 v217.17,8.13 | v223.01,8.13 223.52,8.13 v226.57,5.08
  Bottom 0.305: v149.35,27.18 149.61,26.92 v151.13,26.92 | v217.17,8.13 217.42,7.87 222.76,7.87 v223.01,8.13 | v226.57,5.08 226.82,4.83 236.73,4.83 237.24,5.33 238.25,5.33 239.52,4.06 274.83,4.06 275.59,4.83 v301.24,4.83
N_BAC10  (via drill 0.61)
  Top 0.305: v148.84,3.05 148.84,12.19 149.35,12.7 149.35,21.84 148.84,22.35 148.84,26.16 148.34,26.67 B13.P2 | v279.4,2.79 279.4,12.45 279.15,12.7 279.15,15.75 279.4,16 279.4,18.8 279.15,19.05 279.15,22.1 279.4,22.35 v279.4,25.15 | v282.7,25.15 282.96,25.4 282.96,29.46 282.7,29.72 282.7,30.48 282.96,30.73 282.96,35.81 282.7,36.07 282.7,36.83 282.96,37.08 282.96,42.16 282.7,42.42 282.7,43.18 282.96,43.43 282.96,48.51 282.7,48.77 v282.7,52.07 282.96,52.32 282.96,54.86 282.7,55.12 282.7,59.94 282.19,60.45 282.19,60.96 281.94,61.21 281.94,63.25 v281.69,63.5 | v285.75,105.66 285.75,107.7 285.5,107.95 285.5,110.74 285.75,111 285.75,114.05 285.5,114.3 285.5,117.09 285.75,117.35 285.75,117.86 287.27,119.38 287.27,121.67 A02.E2 | v276.35,88.14 v276.35,104.39 | v281.69,81.53 281.94,81.28 281.94,67.06 v281.69,66.8
  2 0.305: v276.35,88.14 276.35,86.87 v281.69,81.53
  Bottom 0.305: v148.84,3.05 162.05,3.05 162.56,2.54 279.15,2.54 v279.4,2.79 | v279.4,25.15 v282.7,25.15 | v282.7,52.07 284.99,52.07 285.24,52.32 286.77,52.32 B02.E2 | v285.75,105.66 285.24,105.16 284.73,105.16 284.48,104.9 279.4,104.9 278.89,104.39 v276.35,104.39 | v281.69,66.8 282.7,65.79 282.7,63.5 v281.69,63.5
N_BAC11  (via drill 0.61)
  Top 0.305: v152.15,20.57 152.15,19.05 152.4,18.8 152.4,15.75 152.15,15.49 152.15,12.7 152.4,12.45 v152.4,4.06 | v275.84,3.56 275.84,12.45 276.35,12.95 v276.35,26.42 | v279.15,26.42 279.15,28.45 279.4,28.7 279.4,31.5 279.15,31.75 279.15,34.8 279.4,35.05 279.4,37.85 279.15,38.1 279.15,41.15 279.4,41.4 v279.4,44.2 | v288.8,99.82 289.05,100.08 289.05,110.74 288.54,111.25 288.54,115.06 288.04,115.57 A02.H2 | v302.77,85.6 302.51,85.34 302.51,82.3 301.5,81.28 301.5,68.58 302.26,67.82 302.26,63.75 v302.51,63.5 | v294.13,60.45 v294.13,63.25 | v287.27,50.55 287.27,46.74 B02.H2
  2 0.305: v288.8,99.82 298.2,90.42 298.2,90.17 v302.77,85.6
  Bottom 0.305: v152.15,20.57 148.34,20.57 B13.S2 | v152.4,4.06 152.65,3.81 162.31,3.81 162.81,3.3 275.59,3.3 v275.84,3.56 | v276.35,26.42 v279.15,26.42 | v279.4,44.2 282.45,44.2 284.23,45.97 286.77,45.97 B02.H2 | v302.51,63.5 301.5,63.5 301.24,63.25 298.45,63.25 298.2,63.5 295.15,63.5 294.89,63.25 v294.13,63.25 | v294.13,60.45 292.35,60.45 288.54,56.64 288.54,53.85 289.05,53.34 289.05,50.8 288.8,50.8 288.54,50.55 v287.27,50.55
N_BREAK  (via drill 0.61)
  Top 0.305: v134.62,35.05 134.87,35.31 134.87,39.12 B14.K2 | v158.5,31.5 v158.5,34.54 | v210.82,31.5 210.82,29.97 211.07,29.72 211.07,27.69 B08.P2 | v203.2,95 203.2,91.95 202.95,91.69 202.95,88.9 203.2,88.65 203.2,85.6 202.95,85.34 202.95,82.55 203.2,82.3 203.2,66.8 202.95,66.55 202.95,63.5 203.2,63.25 203.2,60.2 202.95,59.94 202.95,57.15 203.2,56.9 203.2,53.85 202.95,53.59 202.95,50.8 203.2,50.55 203.2,47.5 202.95,47.24 202.95,44.45 203.2,44.2 203.2,41.15 202.95,40.89 202.95,38.1 203.2,37.85 203.2,34.8 202.95,34.54 v202.95,31.75
  Bottom 0.305: v134.62,35.05 155.19,35.05 155.7,34.54 v158.5,34.54 | v158.5,31.5 161.8,31.5 162.05,31.75 164.85,31.75 165.1,31.5 168.15,31.5 168.4,31.75 171.2,31.75 171.45,31.5 174.5,31.5 174.75,31.75 177.55,31.75 177.8,31.5 180.85,31.5 181.1,31.75 183.9,31.75 184.15,31.5 187.2,31.5 187.45,31.75 190.25,31.75 190.5,31.5 193.55,31.5 193.8,31.75 196.6,31.75 196.85,31.5 199.9,31.5 200.15,31.75 v202.95,31.75 203.2,31.5 206.25,31.5 206.5,31.75 209.3,31.75 209.55,31.5 v210.82,31.5 | v203.2,95 205.99,95 207.77,96.77 210.57,96.77 A08.P2
N_BRKRQ  (via drill 0.61)
  Top 0.305: A08.K2 211.07,108.97 211.07,105.66 209.8,104.39 209.8,82.55 211.07,81.28 211.07,67.06 212.6,65.53 212.6,44.7 211.07,43.18 211.07,40.39 B08.K2 | v121.67,35.05 121.92,35.31 v121.92,36.83 | v155.7,20.83 155.7,24.13 155.96,24.38 155.96,25.91 159,28.96 v159,30.23 | v172.72,22.61 174.24,24.13 174.24,25.15 174.75,25.65 v174.75,34.54 | v185.42,35.05 186.94,36.58 186.94,37.85 187.45,38.35 v187.45,40.13
  2 0.305: v159,30.23 159.77,29.46 161.54,29.46 165.86,25.15 168.15,25.15 168.66,25.65 168.91,25.4 170.18,25.4 172.72,22.86 v172.72,22.61
  15 0.305: v112.27,34.54 111.76,34.54 103.89,42.42 101.35,42.42 100.58,43.18 B17.J1 | v121.92,36.83 122.68,36.83 124.21,38.35 124.46,38.1 126.75,38.1 128.78,36.07 130.3,36.07 141.22,25.15 142.75,25.15 143.26,25.65 143.51,25.4 145.29,25.4 149.86,20.83 150.88,20.83 152.4,22.35 154.18,22.35 v155.7,20.83
  Bottom 0.305: v112.27,34.54 114.05,34.54 114.55,35.05 v121.67,35.05 | v174.75,34.54 177.55,34.54 178.05,35.05 v185.42,35.05 | v187.45,40.13 188.21,40.89 190.25,40.89 190.75,41.4 205.99,41.4 207.77,39.62 210.57,39.62 B08.K2
N_CAINCR  (via drill 0.61)
  Top 0.305: v100.08,28.19 100.08,29.46 B17.N1 | v155.96,9.91 v155.96,6.35 | v180.59,9.14 180.59,12.45 181.1,12.95 181.1,17.78 181.36,18.03 181.36,23.11 181.1,23.37 181.1,24.13 181.36,24.38 181.36,29.46 181.1,29.72 v181.1,33.27 181.36,33.53 181.36,35.81 181.1,36.07 181.1,36.83 181.36,37.08 181.36,42.16 181.1,42.42 181.1,43.18 181.36,43.43 181.36,46.99 v181.1,47.24 | v186.18,99.82 185.67,100.33 185.67,102.62 A10.M2 | v201.17,85.6 200.91,85.34 200.91,82.3 199.9,81.28 199.9,73.66 v200.15,73.41 | v170.94,73.15 170.69,72.9 170.69,64.01 171.96,62.74 171.96,60.96 171.2,60.2 171.2,57.15 v171.45,56.9
  2 0.305: v186.18,99.82 195.33,90.68 196.09,90.68 v201.17,85.6 | v171.45,56.9 v181.1,47.24
  15 0.305: v100.08,28.19 100.08,27.69 106.17,21.59 106.68,21.59 v121.92,6.35
  Bottom 0.305: v121.92,6.35 122.17,6.6 155.7,6.6 v155.96,6.35 | v155.96,9.91 156.46,9.91 156.72,9.65 161.54,9.65 162.05,9.14 166.12,9.14 166.37,9.4 169.42,9.4 169.67,9.14 v180.59,9.14 | v181.1,33.27 185.17,33.27 B10.M2 | v200.15,73.41 199.9,73.66 177.04,73.66 176.78,73.41 171.2,73.41 v170.94,73.15
N_DATA00  (via drill 0.61)
  Top 0.305: v192.79,66.8 193.04,67.06 193.04,81.79 193.8,82.55 193.8,93.98 194.06,94.23 194.06,99.31 193.8,99.57 193.8,100.33 194.06,100.58 194.06,105.66 193.8,105.92 193.8,106.68 194.06,106.93 194.06,112.01 193.8,112.27 193.8,113.03 194.06,113.28 194.06,118.36 193.8,118.62 193.8,119.38 194.06,119.63 194.06,121.67 194.31,121.92 194.31,124.71 194.56,124.97 A09.D2 | v190.25,66.8 190.25,63.5 190.5,63.25 190.5,60.2 190.25,59.94 190.25,57.15 190.5,56.9 v190.5,55.63
  Bottom 0.305: 191.01,55.63 194.56,55.63 B09.D2 | 191.01,55.63 189.48,54.1 66.8,54.1 65.28,55.63 62.48,55.63 B20.D1 | v190.25,66.8 v192.79,66.8 | v190.5,55.63 191.01,55.63
N_DATA01  (via drill 0.61)
  Top 0.305: v146.05,120.4 146.05,117.35 145.8,117.09 145.8,114.3 146.05,114.05 146.05,111 145.8,110.74 145.8,107.95 146.05,107.7 146.05,104.65 145.8,104.39 145.8,101.6 146.05,101.35 146.05,98.3 145.8,98.04 145.8,95.25 146.05,95 146.05,91.95 145.8,91.69 145.8,88.9 146.05,88.65 146.05,85.6 145.8,85.34 145.8,82.55 146.05,82.3 146.05,68.83 145.8,68.58 145.8,63.5 146.05,63.25 146.05,60.2 145.8,59.94 145.8,57.15 146.05,56.9 146.05,53.85 145.8,53.59 v145.8,51.05
  Bottom 0.305: B09.E2 197.87,52.32 194.06,52.32 192.79,51.05 v145.8,51.05 69.85,51.05 68.58,52.32 65.79,52.32 B20.E1 | v146.05,120.4 148.84,120.4 149.1,120.65 152.15,120.65 152.4,120.4 155.19,120.4 155.45,120.65 158.5,120.65 158.75,120.4 161.54,120.4 161.8,120.65 164.85,120.65 165.1,120.4 167.89,120.4 168.15,120.65 171.2,120.65 171.45,120.4 174.24,120.4 174.5,120.65 177.55,120.65 177.8,120.4 180.59,120.4 180.85,120.65 183.9,120.65 184.15,120.4 186.94,120.4 187.2,120.65 190.25,120.65 190.5,120.4 193.29,120.4 195.07,122.17 197.87,122.17 A09.E2
N_DATA02  (via drill 0.61)
  Top 0.305: v63.25,70.1 63.25,63.5 63.5,63.25 63.5,60.45 63.25,60.2 63.25,57.15 63.5,56.9 63.5,54.1 61.98,52.58 61.98,49.78 B20.F1 | v88.9,79.76 v88.9,70.1 | v102.62,70.36 102.87,70.61 102.87,80.01 v102.62,80.26 | v171.96,78.99 172.21,78.74 172.21,67.56 v171.96,67.31 | v198.37,48.77 198.37,46.74 B09.H2 | v198.12,111.25 198.12,112.78 198.37,113.03 198.37,115.32 A09.H2 | v189.48,107.95 v189.48,110.74 | v155.19,107.95 155.19,104.9 155.7,104.39 155.7,82.55 154.69,81.53 v154.69,77.98
  2 0.305: v179.83,67.31 189.99,57.15 190.25,57.15 190.75,56.64 191.01,56.64 194.06,53.59 194.06,53.09 v198.37,48.77
  15 0.305: v98.3,70.36 v88.9,79.76
  Bottom 0.305: v63.25,70.1 63.5,69.85 88.65,69.85 v88.9,70.1 | v98.3,70.36 98.55,70.61 102.36,70.61 v102.62,70.36 | v102.62,80.26 102.62,79.76 103.63,78.74 119.63,78.74 119.89,78.99 121.41,78.99 122.68,77.72 132.08,77.72 132.33,77.98 v154.69,77.98 160.78,77.98 161.8,78.99 162.81,78.99 163.07,78.74 171.7,78.74 v171.96,78.99 | v171.96,67.31 v179.83,67.31 | v198.12,111.25 190.5,111.25 189.99,110.74 v189.48,110.74 | v189.48,107.95 187.2,107.95 186.94,107.7 184.15,107.7 183.9,107.95 180.85,107.95 180.59,107.7 177.8,107.7 177.55,107.95 174.5,107.95 174.24,107.7 171.45,107.7 171.2,107.95 168.15,107.95 167.89,107.7 165.1,107.7 164.85,107.95 161.8,107.95 161.54,107.7 158.75,107.7 158.5,107.95 v155.19,107.95
N_DATA03  (via drill 0.61)
  Top 0.305: A09.K2 198.37,108.97 198.37,105.66 197.1,104.39 197.1,82.55 198.37,81.28 198.37,67.06 199.9,65.53 199.9,44.7 198.37,43.18 198.37,40.39 B09.K2 198.37,39.12 198.37,36.83 v198.12,36.58 | v126.49,74.42 127,74.93 v127,79.5
  2 0.305: v55.63,57.15 56.9,57.15 57.15,56.9 57.4,56.9 61.47,52.83 61.47,52.58 65.53,48.51 65.53,46.74 B20.H1 | v176.28,57.15 176.53,57.15 182.88,50.8 183.9,50.8 v198.12,36.58
  15 0.305: v49.02,57.15 49.02,58.17 33.27,73.91 v31.75,73.91 | v143.26,79.76 143.76,79.76 149.1,74.42 149.86,74.42 156.72,67.56 159.26,67.56 159.77,68.07 160.78,68.07 170.94,57.91 171.96,57.91 172.97,56.9 174.5,56.9 175.01,57.4 175.26,57.15 v176.28,57.15
  Bottom 0.305: v55.63,57.15 53.85,57.15 53.59,56.9 50.8,56.9 50.55,57.15 v49.02,57.15 | v31.75,73.91 50.04,73.91 50.29,74.17 52.58,74.17 53.09,74.68 56.9,74.68 57.15,74.93 68.58,74.93 68.83,74.68 72.64,74.68 73.15,75.18 78.99,75.18 79.25,74.93 92.2,74.93 92.46,74.68 95,74.68 95.5,75.18 100.08,75.18 100.33,74.93 119.38,74.93 119.63,74.68 126.24,74.68 v126.49,74.42 | v127,79.5 127.25,79.25 131.57,79.25 131.83,79.5 143,79.5 v143.26,79.76
N_DATA04  (via drill 0.61)
  Top 0.305: v82.55,45.47 82.3,45.72 82.3,47.5 82.55,47.75 82.55,52.83 85.34,55.63 85.34,56.9 85.85,57.4 v85.85,79.76 | v198.37,98.55 198.37,102.62 A09.M2 | v189.23,88.9 v189.23,91.69 | v176.53,82.55 v176.53,85.34 | v167.39,82.3 167.64,82.04 167.64,80.26 168.15,79.76 168.15,78.99 168.4,78.74 168.4,63.5 168.15,63.25 v167.64,63.25
  2 0.305: v160.78,63.25 160.78,62.74 170.43,53.09 170.43,52.58 188.47,34.54 v188.98,34.54
  15 0.305: v85.85,79.76 85.85,79.5 v102.11,63.25
  Bottom 0.305: v82.55,45.47 80.52,45.47 79.25,44.2 76.2,44.2 75.95,44.45 73.15,44.45 72.9,44.2 69.85,44.2 69.6,44.45 66.8,44.45 66.55,44.2 65.79,44.2 64.52,42.93 62.48,42.93 B20.J1 | v102.11,63.25 104.65,63.25 104.9,63.5 107.7,63.5 107.95,63.25 111,63.25 111.25,63.5 114.05,63.5 114.3,63.25 117.35,63.25 117.6,63.5 120.4,63.5 120.65,63.25 123.7,63.25 123.95,63.5 126.75,63.5 127,63.25 130.05,63.25 130.3,63.5 133.1,63.5 133.35,63.25 136.4,63.25 136.65,63.5 139.45,63.5 139.7,63.25 142.75,63.25 143,63.5 145.8,63.5 146.05,63.25 149.1,63.25 149.35,63.5 152.15,63.5 152.4,63.25 155.45,63.25 155.7,63.5 158.5,63.5 158.75,63.25 v160.78,63.25 161.04,63.5 164.85,63.5 165.1,63.25 v167.64,63.25 | v188.98,34.54 190.25,34.54 190.75,35.05 193.29,35.05 195.07,33.27 197.87,33.27 B09.M2 | v198.37,98.55 198.63,98.55 200.15,97.03 200.15,95.25 199.9,95.25 199.64,95 196.85,95 196.6,95.25 194.82,95.25 193.8,94.23 192.53,94.23 189.99,91.69 v189.23,91.69 | v189.23,88.9 188.21,88.9 184.4,85.09 184.15,85.09 183.9,84.84 181.61,84.84 180.59,85.85 177.8,85.85 177.29,85.34 v176.53,85.34 | v176.53,82.55 174.5,82.55 174.24,82.3 171.45,82.3 171.2,82.55 168.15,82.55 167.89,82.3 v167.39,82.3
N_DATA05  (via drill 0.61)
  Top 0.305: v66.8,59.94 66.8,44.7 66.29,44.2 66.29,40.64 65.79,40.13 B20.K1 | v91.95,61.47 91.69,61.72 91.69,63.25 92.2,63.75 v92.2,64.52 | v95.25,64.52 95,64.26 95,63.5 95.25,63.25 v95.25,61.47 | v107.95,60.2 107.95,63.25 107.7,63.5 107.7,78.99 107.95,79.25 v107.95,79.76 | v149.35,88.9 149.35,82.8 148.84,82.3 v148.84,78.99 149.1,78.74 v149.1,73.41 | v191.52,30.48 v191.52,28.7
  2 0.305: v191.52,30.48 169.67,52.32 169.67,52.83 v149.1,73.41
  Bottom 0.305: v66.8,59.94 69.6,59.94 70.1,60.45 85.09,60.45 85.6,59.94 88.65,59.94 90.17,61.47 v91.95,61.47 | v95.25,64.52 v92.2,64.52 | v95.25,61.47 95.5,61.21 98.81,61.21 99.57,60.45 104.39,60.45 104.9,59.94 107.7,59.94 v107.95,60.2 | v107.95,79.76 108.2,79.5 119.38,79.5 119.63,79.76 121.67,79.76 122.94,78.49 131.83,78.49 132.08,78.74 148.59,78.74 v148.84,78.99 | v149.35,88.9 152.15,88.9 152.4,88.65 155.45,88.65 155.7,88.9 158.5,88.9 158.75,88.65 161.8,88.65 162.05,88.9 164.85,88.9 165.1,88.65 168.15,88.65 168.4,88.9 171.2,88.9 171.45,88.65 174.5,88.65 174.75,88.9 177.55,88.9 177.8,88.65 179.58,88.65 181.61,90.68 181.61,91.69 181.86,91.69 182.37,92.2 182.88,92.2 183.13,92.46 184.66,92.46 186.18,93.98 186.69,93.98 186.94,94.23 187.2,94.23 188.21,95.25 190.25,95.25 190.5,95 193.55,95 195.33,96.77 197.87,96.77 A09.P2 | v191.52,28.7 193.29,28.7 193.8,28.19 197.61,28.19 198.12,27.69 B09.P2
N_DATA06  (via drill 0.61)
  Top 0.305: v114.3,28.7 114.3,31.5 114.05,31.75 114.05,34.8 114.3,35.05 v114.3,37.85 | v133.35,39.37 133.6,39.62 133.6,40.39 134.11,40.89 134.11,42.16 136.91,44.96 v136.91,45.47 | v145.8,39.88 145.8,41.15 146.05,41.4 v146.05,42.42 | v148.84,42.42 148.84,44.2 149.35,44.7 v149.35,45.72 v149.35,59.94 | v192.79,85.85 v192.79,88.65 | v183.9,80.01 184.15,79.76 184.15,69.09 v183.9,68.83 | v176.78,68.83 176.78,63.75 v176.53,63.5 | v173.48,63.25 v173.48,60.45
  15 0.305: v73.15,28.19 v64.26,37.08 | v136.91,45.47 137.92,44.45 139.45,44.45 v144.02,39.88 | v151.13,45.72 v175.01,21.84 | v188.21,85.34 188.21,84.33 v183.9,80.01
  Bottom 0.305: v64.26,37.08 62.48,37.08 B20.L1 | v73.15,28.19 75.95,28.19 76.45,28.7 98.04,28.7 99.57,27.18 100.58,27.18 102.11,28.7 v114.3,28.7 | v114.3,37.85 117.35,37.85 117.6,38.1 120.4,38.1 120.65,37.85 123.7,37.85 123.95,38.1 129.29,38.1 130.05,38.86 132.84,38.86 v133.35,39.37 | v145.8,39.88 v144.02,39.88 | v148.84,42.42 v146.05,42.42 | v149.35,45.72 v151.13,45.72 | v175.01,21.84 177.55,21.84 178.05,22.35 193.29,22.35 194.56,21.08 195.58,21.08 196.09,21.59 197.87,21.59 198.12,21.34 B09.S2 | v192.79,88.65 193.29,88.65 195.07,90.42 197.87,90.42 A09.S2 | v192.79,85.85 190.5,85.85 189.99,85.34 v188.21,85.34 | v183.9,68.83 v176.78,68.83 | v176.53,63.5 174.5,63.5 174.24,63.25 v173.48,63.25 | v173.48,60.45 171.7,60.45 171.2,59.94 168.4,59.94 167.89,60.45 165.1,60.45 164.59,59.94 161.8,59.94 161.29,60.45 156.72,60.45 156.21,60.96 152.91,60.96 151.89,59.94 v149.35,59.94
N_DATA07  (via drill 0.61)
  Top 0.305: 195.33,68.83 195.33,63.75 196.6,62.48 196.6,22.1 195.33,20.83 195.33,18.03 B09.T2 | 195.33,68.83 195.33,77.98 196.6,79.25 196.6,82.04 195.33,83.31 195.33,86.61 A09.T2 | v63.5,33.27 63.5,36.32 63.25,36.58 v63.25,40.89 | v50.8,98.55 50.8,101.35 47.24,104.9 47.24,108.2 47.75,108.71 47.75,119.38 48.01,119.63 48.01,122.94 v48.77,123.7 | v48.77,130.05 v48.77,127 | v130.3,82.55 v130.3,85.85 | v195.07,68.83 195.33,68.83
  2 0.305: v58.93,130.3 58.93,131.83 59.69,132.59 60.71,132.59 61.47,133.35 61.72,133.35 61.98,133.1 63.25,133.1 68.58,127.76 68.83,127.76 73.15,123.44 75.95,123.44 76.71,124.21 76.96,123.95 77.98,123.95 86.11,115.82 86.11,115.06 86.87,114.3 88.65,114.3 90.68,112.27 v91.95,112.27
  15 0.305: v58.17,42.16 52.07,48.26 51.82,48.26 50.8,49.28 50.8,49.53 47.75,52.58 47.75,53.85 45.47,56.13 45.47,57.4 36.83,66.04 35.81,66.04 25.4,76.45 25.4,82.3 25.15,82.55 25.15,84.58 v26.42,85.85 | v91.95,112.27 95,109.22 95,108.46 101.35,102.11 101.35,101.6 106.68,96.27 106.68,96.01 v117.35,85.34 | v166.12,82.04 179.58,68.58 181.61,68.58 v183.64,66.55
